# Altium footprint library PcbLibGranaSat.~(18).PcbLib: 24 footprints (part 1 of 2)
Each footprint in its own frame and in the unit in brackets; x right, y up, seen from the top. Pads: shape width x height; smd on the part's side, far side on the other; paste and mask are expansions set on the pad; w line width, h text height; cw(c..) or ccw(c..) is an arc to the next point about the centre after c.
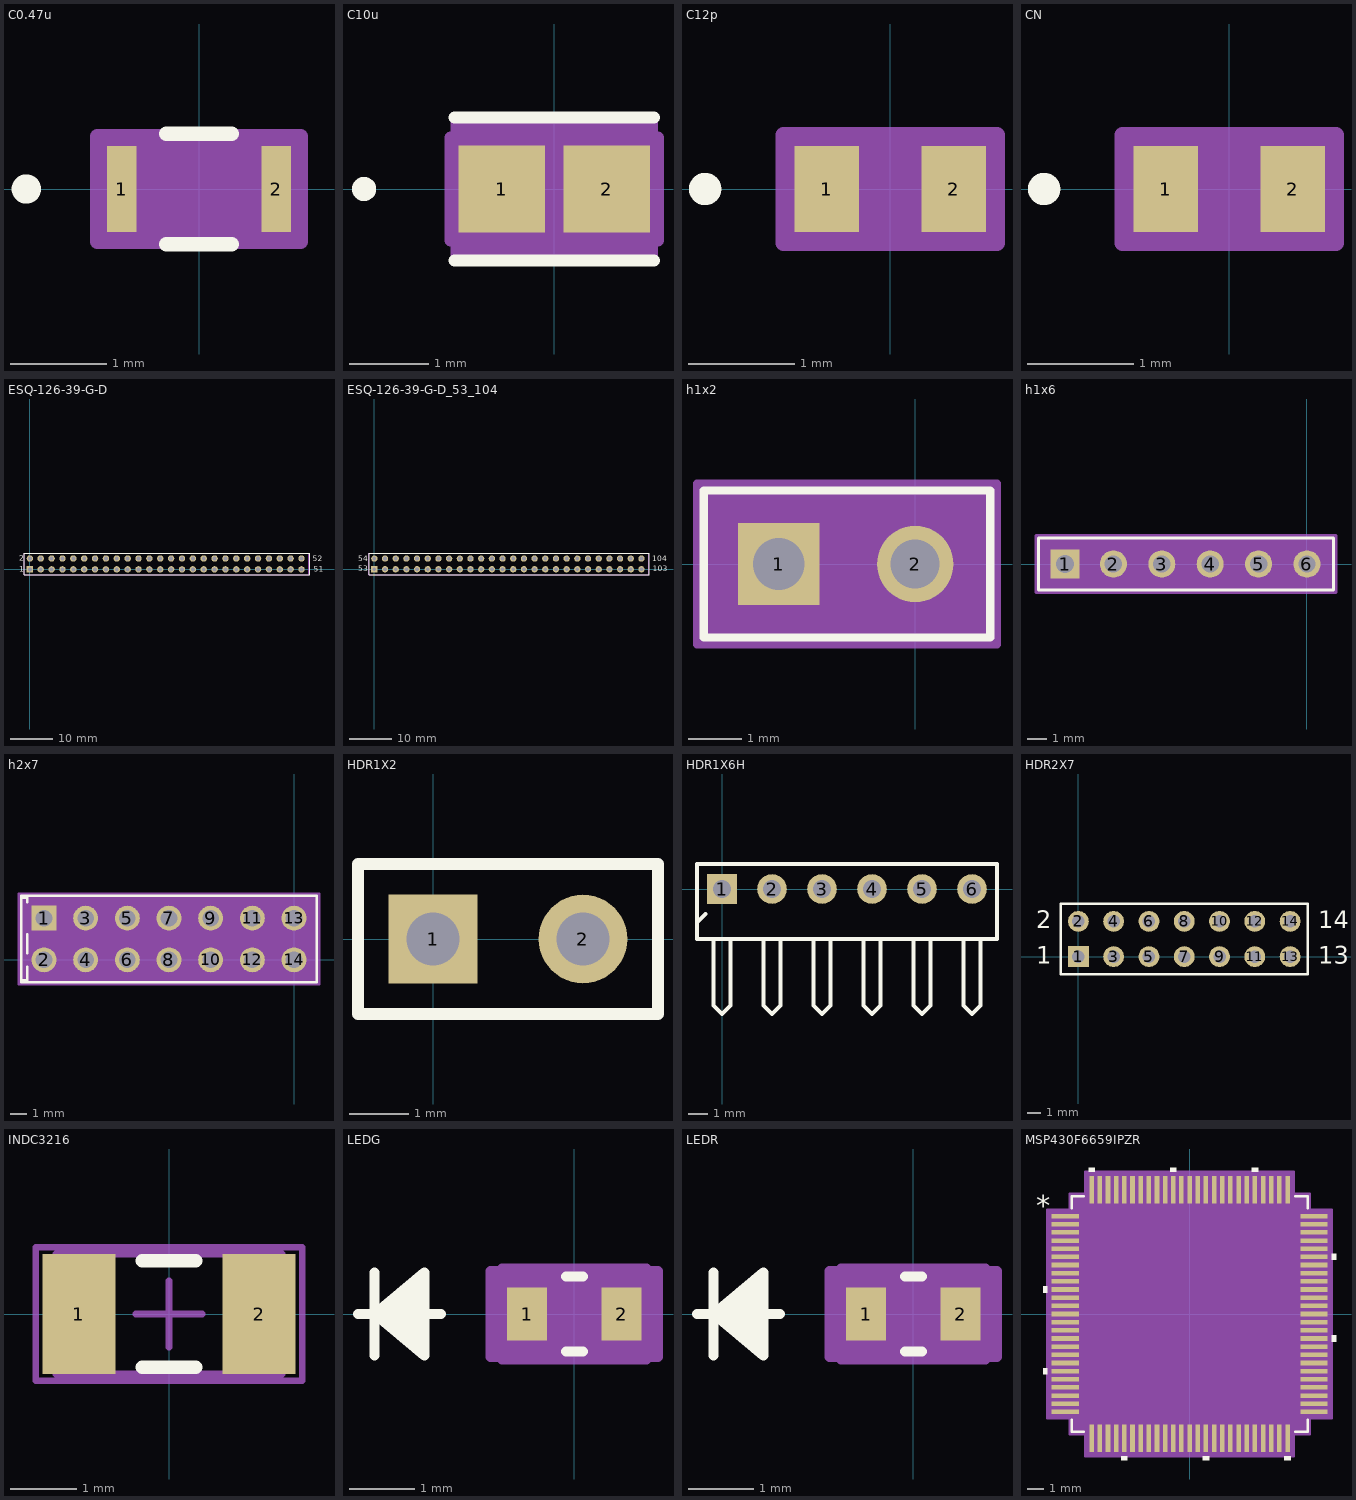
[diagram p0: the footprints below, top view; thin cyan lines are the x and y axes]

## C0.47u [mil]
pads (2):
  rect 12x35 smd paste+0 mask+0: 1(-31.5,0) 2(31.5,0)
Top Overlay:
  circle w6: c-70.5,0 r3
  lines w6: -13.39,-22.5 13.39,-22.5 ; -13.39,22.5 13.39,22.5
Mechanical 13:
  circle w0: c-26.5,0 r3
  lines w1: -33.5,-17.5 -33.5,17.5 ; -33.5,-17.5 33.5,-17.5 ; -33.5,-17.5 -25.5,-17.5 -25.5,17.5 -33.5,17.5 ; -33.5,-17.5 -33.5,17.5 ; -33.5,17.5 33.5,17.5 ; 33.5,-17.5 33.5,17.5 ; 33.5,-17.5 33.5,17.5 ; 33.5,-17.5 25.5,-17.5 25.5,17.5 33.5,17.5
Mechanical 15:
  region: 41.5,-21.5 -41.5,-21.5 -41.5,21.5 41.5,21.5
  lines w6: -41.5,-21.5 41.5,-21.5 41.5,21.5 -41.5,21.5 -41.5,-21.5
3D body: height 10, standoff 0, extent 0,0 10,10

## C10u [mil]
pads (2):
  rect 43x43 smd paste+0 mask+0: 1(-26,0) 2(26,0)
Top Overlay:
  circle w6: c-94.5,0 r3
  lines w6: -49.5,-35.5 49.5,-35.5 ; -49.5,35.5 49.5,35.5
Mechanical 13:
  circle w0: c-34.5,0 r3
  lines w1: -44.5,-30.5 44.5,-30.5 44.5,30.5 -44.5,30.5 -44.5,-30.5
Mechanical 15:
  region: -48.5,-25.5 -51.5,-25.5 -51.5,25.5 -48.5,25.5 -48.5,34.5 48.5,34.5 48.5,25.5 51.5,25.5 51.5,-25.5 48.5,-25.5 48.5,-34.5 -48.5,-34.5
  lines w6: -51.5,-25.5 -51.5,25.5 -48.5,25.5 -48.5,34.5 48.5,34.5 48.5,25.5 51.5,25.5 51.5,-25.5 48.5,-25.5 48.5,-34.5 -48.5,-34.5 -48.5,-25.5 -51.5,-25.5
3D body: height 10, standoff 0, extent 0,0 10,10

## C12p [mil]
pads (2):
  rect 24x32 smd paste+0 mask+0: 1(-23.5,0) 2(23.5,0)
Top Overlay:
  circle w6: c-68.5,0 r3
Mechanical 13:
  circle w0: c-18.5,0 r3
  lines w1: -31.5,-16 -31.5,16 ; -31.5,-16 31.5,-16 ; -31.5,-16 -11.5,-16 -11.5,16 -31.5,16 ; -31.5,-16 -31.5,16 ; -31.5,16 31.5,16 ; 31.5,-16 31.5,16 ; 31.5,-16 31.5,16 ; 31.5,-16 11.5,-16 11.5,16 31.5,16
Mechanical 15:
  region: 39.5,-20 -39.5,-20 -39.5,20 39.5,20
  lines w6: -39.5,-20 39.5,-20 39.5,20 -39.5,20 -39.5,-20
3D body: height 10, standoff 0, extent 0,0 10,10

## CN [mil]
pads (2):
  rect 24x32 smd paste+0 mask+0: 1(-23.5,0) 2(23.5,0)
Top Overlay:
  circle w6: c-68.5,0 r3
Mechanical 13:
  circle w0: c-18.5,0 r3
  lines w1: -31.5,-16 -31.5,16 ; -31.5,-16 31.5,-16 ; -31.5,-16 -11.5,-16 -11.5,16 -31.5,16 ; -31.5,-16 -31.5,16 ; -31.5,16 31.5,16 ; 31.5,-16 31.5,16 ; 31.5,-16 31.5,16 ; 31.5,-16 11.5,-16 11.5,16 31.5,16
Mechanical 15:
  region: 39.5,-20 -39.5,-20 -39.5,20 39.5,20
  lines w6: -39.5,-20 39.5,-20 39.5,20 -39.5,20 -39.5,-20
3D body: height 10, standoff 0, extent 0,0 10,10

## ESQ-126-39-G-D [mm] "Cubesat Connector; Header; 26x2 Position"
pads (52):
  rect 1.5x1.5 hole 0.9: 1(0,0)
  round 1.5 hole 0.9: 2(0,2.54) 3(2.54,0) 4(2.54,2.54) 5(5.08,0) 6(5.08,2.54) 7(7.62,0) 8(7.62,2.54) 9(10.16,0) 10(10.16,2.54) 11(12.7,0) 12(12.7,2.54) 13(15.24,0) 14(15.24,2.54) 15(17.78,0) 16(17.78,2.54) 17(20.32,0) 18(20.32,2.54) 19(22.86,0) 20(22.86,2.54) 21(25.4,0) 22(25.4,2.54) 23(27.94,0) 24(27.94,2.54) 25(30.48,0) 26(30.48,2.54) 27(33.02,0) 28(33.02,2.54) 29(35.56,0) 30(35.56,2.54) 31(38.1,0) 32(38.1,2.54) 33(40.64,0) 34(40.64,2.54) 35(43.18,0) 36(43.18,2.54) 37(45.72,0) 38(45.72,2.54) 39(48.26,0) 40(48.26,2.54) 41(50.8,0) 42(50.8,2.54) 43(53.34,0) 44(53.34,2.54) 45(55.88,0) 46(55.88,2.54) 47(58.42,0) 48(58.42,2.54) 49(60.96,0) 50(60.96,2.54) 51(63.5,0) 52(63.5,2.54)
Top Overlay:
  lines w0.2: -1.27,-1.27 65.38,-1.27 65.38,3.81 -1.27,3.81 -1.27,-1.27
  text "52" at 66.116,1.956 h1.27
  text "51" at 66.319,-0.533 h1.27
  text "1" at -2.54,-0.508 h1.27
  text "2" at -2.54,2.032 h1.27
Mechanical 16:
  lines w0.185: -1.3,-1.3 -1.3,3.8 65.2,3.8 65.2,-1.3 -1.3,-1.3
Mechanical 25:
  text "2" at -0.4,1.7 h1.52
  text "1" at -0.2,-0.8 h1.52
  text "'.Designator'" at 20,0.6 h1.52
3D body "ESQ-126-39-G-D.stp": height 10.51, standoff -12.73, extent -1.295,-1.295 65.253,3.785

## ESQ-126-39-G-D_53_104 [mm] "Cubesat Connector; Header; 26x2 Position"
pads (52):
  rect 1.5x1.5 hole 0.9: 53(0,0)
  round 1.5 hole 0.9: 54(0,2.54) 55(2.54,0) 56(2.54,2.54) 57(5.08,0) 58(5.08,2.54) 59(7.62,0) 60(7.62,2.54) 61(10.16,0) 62(10.16,2.54) 63(12.7,0) 64(12.7,2.54) 65(15.24,0) 66(15.24,2.54) 67(17.78,0) 68(17.78,2.54) 69(20.32,0) 70(20.32,2.54) 71(22.86,0) 72(22.86,2.54) 73(25.4,0) 74(25.4,2.54) 75(27.94,0) 76(27.94,2.54) 77(30.48,0) 78(30.48,2.54) 79(33.02,0) 80(33.02,2.54) 81(35.56,0) 82(35.56,2.54) 83(38.1,0) 84(38.1,2.54) 85(40.64,0) 86(40.64,2.54) 87(43.18,0) 88(43.18,2.54) 89(45.72,0) 90(45.72,2.54) 91(48.26,0) 92(48.26,2.54) 93(50.8,0) 94(50.8,2.54) 95(53.34,0) 96(53.34,2.54) 97(55.88,0) 98(55.88,2.54) 99(58.42,0) 100(58.42,2.54) 101(60.96,0) 102(60.96,2.54) 103(63.5,0) 104(63.5,2.54)
Top Overlay:
  lines w0.2: -1.27,-1.27 65.38,-1.27 65.38,3.81 -1.27,3.81 -1.27,-1.27
  text "104" at 66.116,1.956 h1.27
  text "103" at 66.167,-0.483 h1.27
  text "53" at -3.886,-0.508 h1.27
  text "54" at -3.81,1.905 h1.27
Mechanical 16:
  lines w0.185: -1.3,-1.3 -1.3,3.8 65.2,3.8 65.2,-1.3 -1.3,-1.3
Mechanical 25:
  text "2" at -0.4,1.7 h1.52
  text "1" at -0.2,-0.8 h1.52
  text "'.Designator'" at 20,0.6 h1.52
3D body "ESQ-126-39-G-D.stp": height 10.51, standoff -12.73, extent -1.295,-1.295 65.253,3.785

## h1x2 [mil]
pads (2):
  rect 60x60 hole 38 mask+0: 1(-100,0)
  round 56 hole 36 mask+0: 2(0,0)
Top Overlay:
  lines w6: -155,-54 -155,54 55,54 55,-54 -155,-54
Mechanical 13:
  circle w0: c-100,34 r10
  lines w1: -150,-49 -150,49 50,49 50,-49 -150,-49
Mechanical 15:
  region: 60,59 -160,59 -160,-59 60,-59
  lines w6: -160,-59 60,-59 60,59 -160,59 -160,-59
3D body "22-28-4025.stp": height 450, standoff -200, extent -150,-50 50,50
3D body: height 10, standoff 0, extent 0,0 10,10

## h1x6 [mil]
pads (6):
  rect 60x60 hole 38 mask+0: 1(-500,0)
  round 56 hole 36 mask+0: 2(-400,0) 3(-300,0) 4(-200,0) 5(-100,0) 6(0,0)
Top Overlay:
  lines w6: -555,-54 55,-54 55,54 -555,54 -555,-54
Mechanical 13:
  circle w0: c-500,34 r10
  lines w1: -550,-49 50,-49 50,49 -550,49 -550,-49
Mechanical 15:
  region: 60,59 -560,59 -560,-59 60,-59
  lines w6: -560,-59 -560,59 60,59 60,-59 -560,-59
3D body: height 10, standoff 0, extent 0,0 10,10
3D body "22-28-4066.stp": height 450, standoff -200, extent -550,-50 50,50

## h2x7 [mil]
pads (14):
  rect 60x60 hole 40 mask+0: 1(-600,100)
  round 60 hole 40 mask+0: 2(-600,0) 3(-500,100) 4(-500,0) 5(-400,100) 6(-400,0) 7(-300,100) 8(-300,0) 9(-200,100) 10(-200,0) 11(-100,100) 12(-100,0) 13(0,100) 14(0,0)
Top Overlay:
  lines w6: -650,-48.5 -640,-48.5 -640,-16.05 ; -650,148.5 -640,148.5 -640,138.46 ; -640,16.05 -640,61.54 ; -655,-53.5 -655,153.5 55,153.5 55,-53.5 -655,-53.5
Mechanical 13:
  lines w1: -650,-48.5 -650,148.5 ; -650,-48.5 50,-48.5 50,148.5 -650,148.5 ; -650,-48.5 -640,-48.5 -640,148.5 -650,148.5
Mechanical 15:
  region: 60,158.5 -660,158.5 -660,-58.5 60,-58.5
  lines w6: -660,-58.5 60,-58.5 60,158.5 -660,158.5 -660,-58.5
3D body "CON14_2X7_P100UM_HDR.stp": height 374.02, standoff -200, extent -650,-50 50,150
3D body: height 10, standoff 0, extent 0,0 10,10

## HDR1X2 [mm] "Connector; Header; 2 Position"
pads (2):
  rect 1.5x1.5 hole 0.9: 1(0,0)
  round 1.5 hole 0.9: 2(2.54,0)
Top Overlay:
  lines w0.2: -1.27,-1.27 3.81,-1.27 3.81,1.27 -1.27,1.27 -1.27,-1.27

## HDR1X6H [mm] "Connector; Header; 6 Position; Right Angle"
pads (6):
  rect 1.5x1.5 hole 0.9: 1(0,0)
  round 1.5 hole 0.9: 2(2.54,0) 3(5.08,0) 4(7.62,0) 5(10.16,0) 6(12.7,0)
Top Overlay:
  lines w0.2: -1.27,-1.693 -0.847,-1.27 ; -0.423,-2.54 -0.423,-5.927 0,-6.35 0.423,-5.927 0.423,-2.54 ; 2.117,-2.54 2.117,-5.927 2.54,-6.35 2.963,-5.927 2.963,-2.54 ; 4.657,-2.54 4.657,-5.927 5.08,-6.35 5.503,-5.927 5.503,-2.54 ; 7.197,-2.54 7.197,-5.927 7.62,-6.35 8.043,-5.927 8.043,-2.54 ; 9.737,-2.54 9.737,-5.927 10.16,-6.35 10.583,-5.927 10.583,-2.54 ; 12.277,-2.54 12.277,-5.927 12.7,-6.35 13.123,-5.927 13.123,-2.54 ; -1.27,-2.54 13.97,-2.54 13.97,1.27 -1.27,1.27 -1.27,-2.54

## HDR2X7 [mm] "Connector; Header; 7x2 Position"
pads (14):
  rect 1.5x1.5 hole 0.9: 1(0,0)
  round 1.5 hole 0.9: 2(0,2.54) 3(2.54,0) 4(2.54,2.54) 5(5.08,0) 6(5.08,2.54) 7(7.62,0) 8(7.62,2.54) 9(10.16,0) 10(10.16,2.54) 11(12.7,0) 12(12.7,2.54) 13(15.24,0) 14(15.24,2.54)
Top Overlay:
  lines w0.2: -1.27,-1.27 16.51,-1.27 16.51,3.81 -1.27,3.81 -1.27,-1.27
  text "13" at 17.272,-0.508 h1.27
  text "14" at 17.272,2.032 h1.27
  text "1" at -3.048,-0.508 h1.27
  text "2" at -3.048,2.032 h1.27

## INDC3216 [mm] "Chip Inductor, Body 3.2x1.6mm, IPC High Density"
height 0.55
pads (2):
  rect 1.1x1.8 smd: 1(-1.35,0) 2(1.35,0)
Top Overlay:
  lines w0.2: -0.4,-0.8 0.4,-0.8 ; -0.4,0.8 0.4,0.8
Mechanical 13:
  lines w0.1: -1.7,-0.9 1.7,-0.9 1.7,0.9 -1.7,0.9 -1.7,-0.9
Mechanical 15:
  lines w0.1: -0.5,0 0.5,0 ; 0,-0.5 0,0.5 ; -2,-1 2,-1 2,1 -2,1 -2,-1
3D body: height 0.55, standoff 0, extent -1.7,-0.9 1.7,0.9

## LEDG [mil]
pads (2):
  rect 24x32 smd paste+0 mask+0: 1(-28.5,0) 2(28.5,0)
Top Overlay:
  lines w6: -130.5,0 -80.5,0 ; -120.5,-25 -120.5,25 ; -90.5,-20 -120.5,0 ; -90.5,-15 -120.5,0 ; -90.5,-10 -120.5,0 ; -90.5,-5 -120.5,0 ; -90.5,5 -120.5,0 ; -90.5,10 -120.5,0 ; -90.5,15 -120.5,0 ; -90.5,20 -120.5,0 ; -5.13,-22.5 5.13,-22.5 ; -5.13,22.5 5.13,22.5 ; -120.5,0 -90.5,25 -90.5,-25 -120.5,0
Mechanical 13:
  lines w1: -130.5,0 -80.5,0 ; -120.5,-25 -120.5,25 ; -90.5,-20 -120.5,0 ; -90.5,-15 -120.5,0 ; -90.5,-10 -120.5,0 ; -90.5,-5 -120.5,0 ; -90.5,5 -120.5,0 ; -90.5,10 -120.5,0 ; -90.5,15 -120.5,0 ; -90.5,20 -120.5,0 ; -120.5,0 -90.5,25 -90.5,-25 -120.5,0 ; -33.5,-17.5 33.5,-17.5 33.5,17.5 -33.5,17.5 -33.5,-17.5
Mechanical 15:
  region: -43.5,-26 -50.5,-26 -50.5,26 -43.5,26 -43.5,27.5 43.5,27.5 43.5,26 50.5,26 50.5,-26 43.5,-26 43.5,-27.5 -43.5,-27.5
  lines w6: -50.5,-26 -50.5,26 -43.5,26 -43.5,27.5 43.5,27.5 43.5,26 50.5,26 50.5,-26 43.5,-26 43.5,-27.5 -43.5,-27.5 -43.5,-26 -50.5,-26
3D body: height 10, standoff 0, extent 0,0 10,10

## LEDR [mil]
pads (2):
  rect 24x32 smd paste+0 mask+0: 1(-28.5,0) 2(28.5,0)
Top Overlay:
  lines w6: -130.5,0 -80.5,0 ; -120.5,-25 -120.5,25 ; -90.5,-20 -120.5,0 ; -90.5,-15 -120.5,0 ; -90.5,-10 -120.5,0 ; -90.5,-5 -120.5,0 ; -90.5,5 -120.5,0 ; -90.5,10 -120.5,0 ; -90.5,15 -120.5,0 ; -90.5,20 -120.5,0 ; -5.13,-22.5 5.13,-22.5 ; -5.13,22.5 5.13,22.5 ; -120.5,0 -90.5,-25 -90.5,25 -120.5,0
Mechanical 13:
  lines w1: -130.5,0 -80.5,0 ; -120.5,-25 -120.5,25 ; -90.5,-20 -120.5,0 ; -90.5,-15 -120.5,0 ; -90.5,-10 -120.5,0 ; -90.5,-5 -120.5,0 ; -90.5,5 -120.5,0 ; -90.5,10 -120.5,0 ; -90.5,15 -120.5,0 ; -90.5,20 -120.5,0 ; -120.5,0 -90.5,-25 -90.5,25 -120.5,0 ; -33.5,-17.5 -33.5,17.5 33.5,17.5 33.5,-17.5 -33.5,-17.5
Mechanical 15:
  region: -43.5,-26 -50.5,-26 -50.5,26 -43.5,26 -43.5,27.5 43.5,27.5 43.5,26 50.5,26 50.5,-26 43.5,-26 43.5,-27.5 -43.5,-27.5
  lines w6: -50.5,-26 -43.5,-26 -43.5,-27.5 43.5,-27.5 43.5,-26 50.5,-26 50.5,26 43.5,26 43.5,27.5 -43.5,27.5 -43.5,26 -50.5,26 -50.5,-26
3D body: height 10, standoff 0, extent 0,0 10,10

## MSP430F6659IPZR [mil]
pads (100):
  rect 66x11 smd paste+0 mask+0: 1(-300,236.22) 2(-300,216.54) 3(-300,196.85) 4(-300,177.17) 5(-300,157.48) 6(-300,137.8) 7(-300,118.11) 8(-300,98.43) 9(-300,78.74) 10(-300,59.06) 11(-300,39.37) 12(-300,19.69) 13(-300,0) 14(-300,-19.68) 15(-300,-39.37) 16(-300,-59.06) 17(-300,-78.74) 18(-300,-98.43) 19(-300,-118.11) 20(-300,-137.8) 21(-300,-157.48) 22(-300,-177.17) 23(-300,-196.85) 24(-300,-216.54) 25(-300,-236.22) 51(300,-236.22) 52(300,-216.54) 53(300,-196.85) 54(300,-177.17) 55(300,-157.48) 56(300,-137.8) 57(300,-118.11) 58(300,-98.43) 59(300,-78.74) 60(300,-59.06) 61(300,-39.37) 62(300,-19.68) 63(300,0) 64(300,19.68) 65(300,39.37) 66(300,59.06) 67(300,78.74) 68(300,98.43) 69(300,118.11) 70(300,137.8) 71(300,157.48) 72(300,177.17) 73(300,196.85) 74(300,216.54) 75(300,236.22)
  rect 11x66 smd paste+0 mask+0: 26(-236.22,-300) 27(-216.54,-300) 28(-196.85,-300) 29(-177.17,-300) 30(-157.48,-300) 31(-137.8,-300) 32(-118.11,-300) 33(-98.43,-300) 34(-78.74,-300) 35(-59.06,-300) 36(-39.37,-300) 37(-19.68,-300) 38(0,-300) 39(19.68,-300) 40(39.37,-300) 41(59.06,-300) 42(78.74,-300) 43(98.43,-300) 44(118.11,-300) 45(137.8,-300) 46(157.48,-300) 47(177.17,-300) 48(196.85,-300) 49(216.54,-300) 50(236.22,-300) 76(236.22,300) 77(216.54,300) 78(196.85,300) 79(177.17,300) 80(157.48,300) 81(137.8,300) 82(118.11,300) 83(98.43,300) 84(78.74,300) 85(59.06,300) 86(39.37,300) 87(19.68,300) 88(0,300) 89(-19.68,300) 90(-39.37,300) 91(-59.06,300) 92(-78.74,300) 93(-98.43,300) 94(-118.11,300) 95(-137.8,300) 96(-157.48,300) 97(-177.17,300) 98(-196.85,300) 99(-216.54,300) 100(-236.22,300)
Top Overlay:
  region: -228.72,343 -243.72,343 -243.72,353 -228.72,353
  region: -31.87,343 -46.87,343 -46.87,353 -31.87,353
  region: 164.98,343 149.98,343 149.98,353 164.98,353
  region: 343,145.3 353,145.3 353,130.3 343,130.3
  region: 343,-51.56 353,-51.56 353,-66.56 343,-66.56
  region: 243.72,-343 228.72,-343 228.72,-353 243.72,-353
  region: 46.87,-343 31.87,-343 31.87,-353 46.87,-353
  region: -149.98,-343 -164.98,-343 -164.98,-353 -149.98,-353
  region: -343,-130.3 -353,-130.3 -353,-145.3 -343,-145.3
  region: -343,66.56 -353,66.56 -353,51.56 -343,51.56
  lines w6: -284.5,-254.82 -284.5,-284.5 -254.82,-284.5 ; -284.5,254.82 -284.5,284.5 -254.82,284.5 ; 254.82,-284.5 284.5,-284.5 284.5,-254.82 ; 254.82,284.5 284.5,284.5 284.5,254.82
  text "*" at -370.5,236.06 h50
Mechanical 13:
  drawing of 405 lines, arcs and shapes, not listed
  text "*" at -277,221.06 h50
Mechanical 15:
  region: -251.72,-289.5 -289.5,-289.5 -289.5,-251.72 -343,-251.72 -343,251.72 -289.5,251.72 -289.5,289.5 -251.72,289.5 -251.72,343 251.72,343 251.72,289.5 289.5,289.5 289.5,251.72 343,251.72 343,-251.72 289.5,-251.72 289.5,-289.5 251.72,-289.5 251.72,-343 -251.72,-343
  lines w6: -343,-251.72 -343,251.72 -289.5,251.72 -289.5,289.5 -251.72,289.5 -251.72,343 251.72,343 251.72,289.5 289.5,289.5 289.5,251.72 343,251.72 343,-251.72 289.5,-251.72 289.5,-289.5 251.72,-289.5 251.72,-343 -251.72,-343 -251.72,-289.5 -289.5,-289.5 -289.5,-251.72 -343,-251.72
3D body "PZ100.stp": height 63.11, standoff 0, extent -318.03,-319.02 320,319.02
3D body: height 10, standoff 0, extent 0,0 10,10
